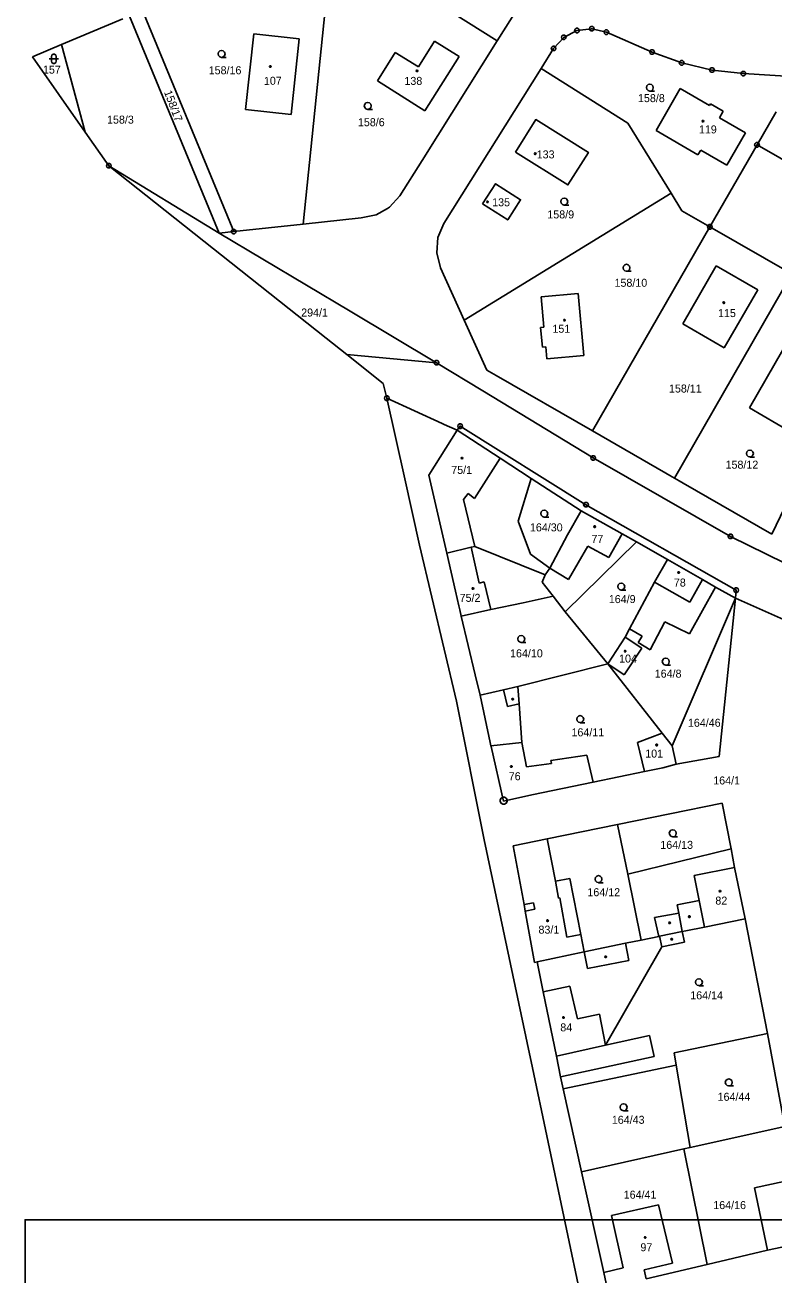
# Model space of a CAD drawing. Extents: x -779723 to -777378, y -1011169 to -1009297.
# Drawn here: x -779530.7 to -779371.6, y -1010279.6 to -1010014.1 of the extents above; entities that cross this region are included whole.
import ezdxf

# ---------------------------------------------------------------- set-up
doc = ezdxf.new("R2010")
doc.units = 0
for name, color, linetype in [('Default', 7, 'Continuous'), ('KN_HRANICE', 7, 'Continuous'), ('KN_KULTURY', 7, 'Continuous'), ('KN_PARCELY', 7, 'Continuous'), ('KN_SLUCKY', 7, 'Continuous'), ('LEGENDA', 7, 'Continuous')]:
    doc.layers.add(name, color=color, linetype=linetype)

# ---------------------------------------------------------------- blocks, each defined once
blk = doc.blocks.new('101')
at = {"layer": 'Default'}
blk.add_line((-0.05, 0), (0.05, 0), dxfattribs=at)
blk.add_lwpolyline([(0.19, 0.72), (0.53, 0.53), (0.72, 0.19), (0.72, -0.2), (0.53, -0.54), (0.19, -0.73), (-0.2, -0.73), (-0.54, -0.54), (-0.73, -0.2), (-0.73, 0.19), (-0.54, 0.53), (-0.2, 0.72), (0.19, 0.72)], dxfattribs=at)
blk = doc.blocks.new('304')
at = {"layer": 'Default'}
blk.add_lwpolyline([(0, 0), (-0.38, 0.1), (-0.65, 0.37), (-0.75, 0.74), (-0.65, 1.11), (-0.38, 1.38), (-0.01, 1.48), (0.36, 1.38), (0.63, 1.11), (0.73, 0.73), (0.63, 0.35), (0.36, 0.08), (-0.02, -0.02), (0.98, -0.02)], dxfattribs=at)
blk = doc.blocks.new('316')
at = {"layer": 'Default'}
for points in [[(-1, 1), (0.27, 1), (1, 1)], [(-0.5, 1.5), (-0.4, 1.79), (-0.15, 1.97), (0.16, 1.97), (0.41, 1.79), (0.51, 1.5), (0.51, 0.5), (0.41, 0.21), (0.16, 0.03), (-0.15, 0.03), (-0.4, 0.21), (-0.5, 0.5), (-0.5, 1.5)]]:
    blk.add_lwpolyline(points, dxfattribs=at)
blk = doc.blocks.new('402')
at = {"layer": 'Default'}
blk.add_lwpolyline([(0.09, 0.15), (0.18, 0), (0.09, -0.15), (-0.09, -0.15), (-0.18, 0), (-0.09, 0.15), (0.09, 0.15)], dxfattribs=at)
blk = doc.blocks.new('105')
at = {"layer": 'Default'}
blk.add_line((-0.12, 0), (0.12, 0), dxfattribs=at)
blk.add_lwpolyline([(0.15, 0.48), (0.4, 0.3), (0.5, 0.01), (0.4, -0.28), (0.15, -0.46), (-0.16, -0.46), (-0.41, -0.28), (-0.51, 0.01), (-0.41, 0.3), (-0.16, 0.48), (0.15, 0.48)], dxfattribs=at)

msp = doc.modelspace()

# ---------------------------------------------------------------- linework, layer by layer
at = {"layer": 'KN_HRANICE'}
for p, q in [((-779430.36, -1010017.45), (-779405.63, -1009978.11)), ((-779466.49, -1010007.04), (-779471.6, -1010056.37)), ((-779505.72, -1010011.01), (-779486.32, -1010057.97)), ((-779430.36, -1010017.45), (-779443.07, -1010009.46)), ((-779522.9, -1010018.23), (-779509.9, -1010012.78)), ((-779508.48, -1010012.18), (-779489.42, -1010058.31)), ((-779483.83, -1010032.01), (-779482.07, -1010015.94)), ((-779482.07, -1010015.94), (-779472.39, -1010016.99)), ((-779416.21, -1010016.69), (-779413.4, -1010015.24)), ((-779413.4, -1010015.24), (-779410.26, -1010014.85)), ((-779410.26, -1010014.85), (-779407.15, -1010015.59)), ((-779407.15, -1010015.59), (-779397.45, -1010019.81)), ((-779529.07, -1010020.81), (-779522.9, -1010018.23)), ((-779522.9, -1010018.23), (-779517.85, -1010036.84)), ((-779472.39, -1010016.99), (-779474.14, -1010033.11)), ((-779447.1, -1010022.98), (-779443.68, -1010017.51)), ((-779443.68, -1010017.51), (-779438.46, -1010020.79)), ((-779421.04, -1010023.31), (-779418.36, -1010019.05)), ((-779418.36, -1010019.05), (-779416.21, -1010016.69)), ((-779517.85, -1010036.84), (-779529.07, -1010020.81)), ((-779455.79, -1010025.95), (-779452.01, -1010019.89)), ((-779452.01, -1010019.89), (-779447.1, -1010022.98)), ((-779438.46, -1010020.79), (-779445.71, -1010032.28)), ((-779397.45, -1010019.81), (-779391.16, -1010022.12)), ((-779441.71, -1010056.21), (-779421.04, -1010023.31)), ((-779402.59, -1010034.91), (-779421.04, -1010023.31)), ((-779391.16, -1010022.12), (-779384.71, -1010023.64)), ((-779384.71, -1010023.64), (-779378.05, -1010024.4)), ((-779445.71, -1010032.28), (-779455.79, -1010025.95)), ((-779378.05, -1010024.4), (-779366.83, -1010025.07)), ((-779391.47, -1010027.58), (-779396.61, -1010036.51)), ((-779385.28, -1010031.16), (-779391.47, -1010027.58)), ((-779474.14, -1010033.11), (-779483.83, -1010032.01)), ((-779385.04, -1010030.79), (-779385.28, -1010031.16)), ((-779382.33, -1010032.39), (-779385.04, -1010030.79)), ((-779393.43, -1010049.78), (-779402.59, -1010034.91)), ((-779383.14, -1010033.8), (-779382.33, -1010032.39)), ((-779377.61, -1010036.95), (-779383.14, -1010033.8)), ((-779375.15, -1010039.53), (-779371.1, -1010032.49)), ((-779512.85, -1010043.97), (-779517.85, -1010036.84)), ((-779396.61, -1010036.51), (-779387.72, -1010041.66)), ((-779381.6, -1010043.83), (-779377.61, -1010036.95)), ((-779385.17, -1010056.96), (-779375.15, -1010039.53)), ((-779375.15, -1010039.53), (-779361.56, -1010047.34)), ((-779387.72, -1010041.66), (-779387.12, -1010040.63)), ((-779387.12, -1010040.63), (-779381.6, -1010043.83)), ((-779489.42, -1010058.31), (-779512.85, -1010043.97)), ((-779466.67, -1010080.62), (-779512.85, -1010043.97)), ((-779451.04, -1010050.34), (-779453.2, -1010052.79)), ((-779437.34, -1010076.8), (-779393.43, -1010049.78)), ((-779391.11, -1010053.54), (-779393.43, -1010049.78)), ((-779385.17, -1010056.96), (-779391.11, -1010053.54)), ((-779459.24, -1010055.03), (-779471.6, -1010056.37)), ((-779456.04, -1010054.41), (-779459.24, -1010055.03)), ((-779441.71, -1010056.21), (-779442.97, -1010059.22)), ((-779486.32, -1010057.97), (-779489.42, -1010058.31)), ((-779489.42, -1010058.31), (-779461.6, -1010074.87)), ((-779471.6, -1010056.37), (-779486.32, -1010057.97)), ((-779410.1, -1010100.31), (-779385.17, -1010056.96)), ((-779385.17, -1010056.96), (-779367.78, -1010066.96)), ((-779442.97, -1010059.22), (-779443.2, -1010062.48)), ((-779443.2, -1010062.48), (-779442.37, -1010065.63)), ((-779442.37, -1010065.63), (-779437.34, -1010076.8)), ((-779390.94, -1010077.53), (-779383.8, -1010065.23)), ((-779383.8, -1010065.23), (-779374.99, -1010070.35)), ((-779392.71, -1010110.31), (-779367.78, -1010066.96)), ((-779420.98, -1010071.8), (-779413.13, -1010071.11)), ((-779420.44, -1010078.28), (-779420.98, -1010071.8)), ((-779413.13, -1010071.11), (-779411.92, -1010084.25)), ((-779374.99, -1010070.35), (-779382.13, -1010082.68)), ((-779461.6, -1010074.87), (-779443.22, -1010085.81)), ((-779437.34, -1010076.8), (-779432.57, -1010087.39)), ((-779371.98, -1010122.22), (-779350.39, -1010076.96)), ((-779421.12, -1010078.36), (-779420.44, -1010078.28)), ((-779420.75, -1010082.53), (-779421.12, -1010078.36)), ((-779382.13, -1010082.68), (-779390.94, -1010077.53)), ((-779462.29, -1010084.1), (-779466.67, -1010080.62)), ((-779420.01, -1010082.47), (-779420.75, -1010082.53)), ((-779419.8, -1010084.97), (-779420.01, -1010082.47)), ((-779443.22, -1010085.81), (-779462.29, -1010084.1)), ((-779454.55, -1010090.24), (-779462.29, -1010084.1)), ((-779411.92, -1010084.25), (-779419.8, -1010084.97)), ((-779376.78, -1010095.43), (-779369.65, -1010083.1)), ((-779443.22, -1010085.81), (-779433.43, -1010091.77)), ((-779453.79, -1010093.36), (-779454.55, -1010090.24)), ((-779449.96, -1010110.52), (-779453.79, -1010093.36)), ((-779433.43, -1010091.77), (-779409.97, -1010106.05)), ((-779368.02, -1010100.51), (-779376.78, -1010095.43)), ((-779444.86, -1010109.68), (-779438.86, -1010100.16)), ((-779438.86, -1010100.16), (-779431.13, -1010105.19)), ((-779431.13, -1010105.19), (-779429.69, -1010106.11)), ((-779423.11, -1010110.38), (-779429.69, -1010106.11)), ((-779409.97, -1010106.05), (-779380.8, -1010122.72)), ((-779446.83, -1010124.56), (-779449.96, -1010110.52)), ((-779441.05, -1010126.3), (-779444.86, -1010109.68)), ((-779425.9, -1010119.46), (-779423.11, -1010110.38)), ((-779412.49, -1010117.26), (-779423.11, -1010110.38)), ((-779415.42, -1010122.39), (-779412.49, -1010117.26)), ((-779412.49, -1010117.26), (-779403.77, -1010122.18)), ((-779425.9, -1010119.46), (-779423.3, -1010126.5)), ((-779415.42, -1010122.39), (-779419.17, -1010129.45)), ((-779403.77, -1010122.18), (-779400.78, -1010123.88)), ((-779439.02, -1010157.72), (-779446.83, -1010124.56)), ((-779441.05, -1010126.3), (-779435.89, -1010125.03)), ((-779435.89, -1010125.03), (-779435.11, -1010124.84)), ((-779435.11, -1010124.84), (-779420.18, -1010130.88)), ((-779415.89, -1010138.74), (-779400.78, -1010123.88)), ((-779394.14, -1010127.63), (-779400.78, -1010123.88)), ((-779380.8, -1010122.72), (-779356.88, -1010134.5)), ((-779439.21, -1010134.38), (-779441.05, -1010126.3)), ((-779419.17, -1010129.45), (-779423.3, -1010126.5)), ((-779396.93, -1010132.43), (-779394.14, -1010127.63)), ((-779386.76, -1010131.89), (-779394.14, -1010127.63)), ((-779419.17, -1010129.45), (-779420.18, -1010130.88)), ((-779420.18, -1010130.88), (-779420.81, -1010132.43)), ((-779420.81, -1010132.43), (-779418.47, -1010135.43)), ((-779396.93, -1010132.43), (-779402.22, -1010142.37)), ((-779386.76, -1010131.89), (-779384.01, -1010133.48)), ((-779438.5, -1010137.45), (-779439.21, -1010134.38)), ((-779424.85, -1010136.8), (-779418.47, -1010135.43)), ((-779415.89, -1010138.74), (-779418.47, -1010135.43)), ((-779393.19, -1010167.19), (-779379.75, -1010135.84)), ((-779384.01, -1010133.48), (-779389.49, -1010143.43)), ((-779384.01, -1010133.48), (-779379.75, -1010135.84)), ((-779379.75, -1010135.84), (-779383.22, -1010169.47)), ((-779379.75, -1010135.84), (-779368.25, -1010140.93)), ((-779438.29, -1010138.35), (-779438.5, -1010137.45)), ((-779438.03, -1010139.63), (-779438.29, -1010138.35)), ((-779431.67, -1010138.26), (-779438.03, -1010139.63)), ((-779424.85, -1010136.8), (-779431.67, -1010138.26)), ((-779438.03, -1010139.63), (-779435, -1010152.13)), ((-779415.89, -1010138.74), (-779406.87, -1010149.81)), ((-779394.77, -1010140.85), (-779397.87, -1010146.79)), ((-779389.49, -1010143.43), (-779394.77, -1010140.85)), ((-779402.22, -1010142.37), (-779403.16, -1010144.15)), ((-779399.58, -1010143.89), (-779402.22, -1010142.37)), ((-779406.87, -1010149.81), (-779403.16, -1010144.15)), ((-779399.6, -1010146.43), (-779403.35, -1010152.12)), ((-779403.16, -1010144.15), (-779399.6, -1010146.43)), ((-779400.38, -1010145.27), (-779399.58, -1010143.89)), ((-779397.87, -1010146.79), (-779400.38, -1010145.27)), ((-779425.97, -1010154.58), (-779406.87, -1010149.81)), ((-779403.35, -1010152.12), (-779406.87, -1010149.81)), ((-779406.87, -1010149.81), (-779395.28, -1010164.54)), ((-779435, -1010152.13), (-779433.96, -1010156.43)), ((-779433.96, -1010156.43), (-779428.99, -1010155.28)), ((-779433.96, -1010156.43), (-779431.85, -1010166.47)), ((-779428.99, -1010155.28), (-779425.97, -1010154.58)), ((-779425.7, -1010158.32), (-779425.97, -1010154.58)), ((-779433.12, -1010187.16), (-779439.02, -1010157.72)), ((-779425.12, -1010166.48), (-779425.7, -1010158.32)), ((-779400.55, -1010166.52), (-779395.28, -1010164.54)), ((-779395.28, -1010164.54), (-779393.19, -1010167.19)), ((-779431.85, -1010166.47), (-779431.68, -1010167.23)), ((-779431.68, -1010167.23), (-779431.65, -1010167.35)), ((-779431.65, -1010167.35), (-779429.01, -1010178.94)), ((-779425.12, -1010166.48), (-779424.13, -1010171.7)), ((-779399.03, -1010172.67), (-779400.55, -1010166.52)), ((-779393.19, -1010167.19), (-779392.31, -1010171.12)), ((-779418.94, -1010170.34), (-779411.28, -1010169.22)), ((-779418.85, -1010170.93), (-779418.94, -1010170.34)), ((-779411.28, -1010169.22), (-779409.96, -1010174.94)), ((-779392.31, -1010171.12), (-779383.22, -1010169.47)), ((-779424.13, -1010171.7), (-779418.85, -1010170.93)), ((-779399.03, -1010172.67), (-779409.96, -1010174.94)), ((-779395.19, -1010171.87), (-779399.03, -1010172.67)), ((-779395.19, -1010171.87), (-779392.31, -1010171.12)), ((-779409.96, -1010174.94), (-779423, -1010177.65)), ((-779429.01, -1010178.94), (-779423, -1010177.65)), ((-779404.79, -1010183.9), (-779382.53, -1010179.37)), ((-779382.53, -1010179.37), (-779380.62, -1010189.12)), ((-779419.77, -1010186.97), (-779404.79, -1010183.9)), ((-779404.79, -1010183.9), (-779402.63, -1010194.49)), ((-779423.51, -1010232.67), (-779433.12, -1010187.16)), ((-779426.94, -1010188.44), (-779419.77, -1010186.97)), ((-779426.94, -1010188.44), (-779424.65, -1010200.94)), ((-779418, -1010195.98), (-779419.77, -1010186.97)), ((-779380.62, -1010189.12), (-779402.63, -1010194.49)), ((-779380.62, -1010189.12), (-779379.91, -1010193.08)), ((-779379.91, -1010193.08), (-779377.71, -1010203.99)), ((-779418, -1010195.98), (-779414.94, -1010195.39)), ((-779414.94, -1010195.39), (-779412.61, -1010207.26)), ((-779402.63, -1010194.49), (-779399.78, -1010208.48)), ((-779424.65, -1010200.94), (-779424.4, -1010202.32)), ((-779424.4, -1010202.32), (-779422.41, -1010213.23)), ((-779377.71, -1010203.99), (-779386.3, -1010205.71)), ((-779377.71, -1010203.99), (-779372.96, -1010228.31)), ((-779412.61, -1010207.26), (-779411.88, -1010211.01)), ((-779391.03, -1010206.67), (-779395.84, -1010207.67)), ((-779390.31, -1010206.52), (-779391.03, -1010206.67)), ((-779390.58, -1010208.93), (-779391.03, -1010206.67)), ((-779386.3, -1010205.71), (-779390.31, -1010206.52)), ((-779411.88, -1010211.01), (-779403.09, -1010209.16)), ((-779407.33, -1010230.83), (-779395.35, -1010209.92)), ((-779403.09, -1010209.16), (-779399.78, -1010208.48)), ((-779399.78, -1010208.48), (-779396.04, -1010207.71)), ((-779395.84, -1010207.67), (-779396.04, -1010207.71)), ((-779395.35, -1010209.92), (-779390.58, -1010208.93)), ((-779421.87, -1010213.12), (-779411.88, -1010211.01)), ((-779422.41, -1010213.23), (-779421.87, -1010213.12)), ((-779421.87, -1010213.12), (-779420.58, -1010219.44)), ((-779420.58, -1010219.44), (-779417.77, -1010233.17)), ((-779407.33, -1010230.83), (-779397.99, -1010228.74)), ((-779396.99, -1010233.24), (-779397.99, -1010228.74)), ((-779372.96, -1010228.31), (-779392.78, -1010232.41)), ((-779369.26, -1010248.05), (-779372.96, -1010228.31)), ((-779423.17, -1010234.28), (-779423.51, -1010232.67)), ((-779417.77, -1010233.17), (-779416.88, -1010237.53)), ((-779416.88, -1010237.53), (-779396.99, -1010233.24)), ((-779392.32, -1010235.07), (-779392.78, -1010232.41)), ((-779411.57, -1010289.24), (-779423.17, -1010234.28)), ((-779416.36, -1010240.08), (-779392.32, -1010235.07)), ((-779389.34, -1010252.55), (-779392.32, -1010235.07)), ((-779416.88, -1010237.53), (-779416.36, -1010240.08)), ((-779416.36, -1010240.08), (-779412.45, -1010257.73)), ((-779369.26, -1010248.05), (-779389.34, -1010252.55)), ((-779389.34, -1010252.55), (-779390.67, -1010252.85)), ((-779390.67, -1010252.85), (-779412.45, -1010257.73)), ((-779385.75, -1010277.38), (-779390.67, -1010252.85)), ((-779412.45, -1010257.73), (-779407.72, -1010279.08)), ((-779375.67, -1010261.12), (-779366.85, -1010259.23)), ((-779372.96, -1010274.36), (-779375.67, -1010261.12)), ((-779406.08, -1010266.98), (-779396.07, -1010264.73)), ((-779396.07, -1010264.73), (-779393.09, -1010277.12)), ((-779406.08, -1010266.98), (-779403.57, -1010278.12)), ((-779363.99, -1010272.5), (-779372.96, -1010274.36)), ((-779372.96, -1010274.36), (-779385.75, -1010277.38)), ((-779407.72, -1010279.08), (-779403.57, -1010278.12)), ((-779407.72, -1010279.08), (-779406.99, -1010282.4)), ((-779399.16, -1010278.51), (-779393.09, -1010277.12)), ((-779399.16, -1010278.51), (-779398.69, -1010280.44)), ((-779385.75, -1010277.38), (-779398.69, -1010280.44))]:
    msp.add_line(p, q, dxfattribs=at)
for points in [[(-779430.36, -1010017.45), (-779446.32, -1010042.84), (-779451.04, -1010050.34)], [(-779453.2, -1010052.79), (-779453.68, -1010053.07), (-779456.04, -1010054.41)], [(-779432.57, -1010087.39), (-779430.6, -1010088.52), (-779410.1, -1010100.31)], [(-779453.79, -1010093.36), (-779442.04, -1010098.71), (-779441.59, -1010098.92), (-779438.86, -1010100.16)], [(-779410.1, -1010100.31), (-779394.52, -1010109.27), (-779393.65, -1010109.77), (-779392.71, -1010110.31)], [(-779392.71, -1010110.31), (-779391.69, -1010110.89), (-779390.82, -1010111.39), (-779371.98, -1010122.22)]]:
    msp.add_lwpolyline(points, dxfattribs=at)
for points in [[(-779426.49, -1010041.07), (-779422.15, -1010034.15), (-779410.97, -1010041.14), (-779415.34, -1010048.05)], [(-779433.48, -1010052.09), (-779430.71, -1010047.79), (-779425.37, -1010051.19), (-779428.1, -1010055.49)]]:
    msp.add_lwpolyline(points, close=True, dxfattribs=at)
at = {"layer": 'KN_SLUCKY'}
for p, q in [((-779438.22, -1010099.31), (-779438.86, -1010100.16)), ((-779411.49, -1010115.98), (-779438.22, -1010099.31)), ((-779429.69, -1010106.11), (-779435.16, -1010114.65)), ((-779436.55, -1010113.62), (-779437.52, -1010114.87)), ((-779435.16, -1010114.65), (-779436.55, -1010113.62)), ((-779437.52, -1010114.87), (-779435.11, -1010124.84)), ((-779379.59, -1010134.15), (-779411.49, -1010115.98)), ((-779403.77, -1010122.18), (-779406.62, -1010127.23)), ((-779434.17, -1010132.62), (-779435.89, -1010125.03)), ((-779415.18, -1010131.88), (-779411.09, -1010124.77)), ((-779411.09, -1010124.77), (-779406.62, -1010127.23)), ((-779419.17, -1010129.45), (-779415.18, -1010131.88)), ((-779433.09, -1010132.38), (-779434.17, -1010132.62)), ((-779431.67, -1010138.26), (-779433.09, -1010132.38)), ((-779396.93, -1010132.43), (-779389.44, -1010136.7)), ((-779389.44, -1010136.7), (-779386.76, -1010131.89)), ((-779379.75, -1010135.84), (-779379.59, -1010134.15)), ((-779428.99, -1010155.28), (-779428.14, -1010158.86)), ((-779428.14, -1010158.86), (-779425.7, -1010158.32)), ((-779431.68, -1010167.23), (-779425.12, -1010166.48)), ((-779379.91, -1010193.08), (-779388.53, -1010194.78)), ((-779417.3, -1010199.54), (-779418, -1010195.98)), ((-779388.53, -1010194.78), (-779387.44, -1010200.1)), ((-779417.3, -1010199.54), (-779417.02, -1010199.49)), ((-779417.02, -1010199.49), (-779415.55, -1010207.86)), ((-779424.65, -1010200.94), (-779422.61, -1010200.55)), ((-779424.4, -1010202.32), (-779422.35, -1010201.94)), ((-779422.35, -1010201.94), (-779422.61, -1010200.55)), ((-779392.14, -1010201.01), (-779387.44, -1010200.1)), ((-779391.8, -1010202.74), (-779392.14, -1010201.01)), ((-779387.44, -1010200.1), (-779386.3, -1010205.71)), ((-779396.93, -1010203.68), (-779391.8, -1010202.74)), ((-779396.93, -1010203.68), (-779396.04, -1010207.71)), ((-779391.03, -1010206.67), (-779391.8, -1010202.74)), ((-779415.55, -1010207.86), (-779412.61, -1010207.26)), ((-779403.09, -1010209.16), (-779402.38, -1010212.79)), ((-779395.84, -1010207.67), (-779395.35, -1010209.92)), ((-779411.88, -1010211.01), (-779411.2, -1010214.51)), ((-779411.2, -1010214.51), (-779402.38, -1010212.79)), ((-779420.58, -1010219.44), (-779414.92, -1010218.29)), ((-779413.31, -1010225.22), (-779414.92, -1010218.29)), ((-779413.31, -1010225.22), (-779408.6, -1010224.25)), ((-779407.33, -1010230.83), (-779408.6, -1010224.25)), ((-779417.77, -1010233.17), (-779407.33, -1010230.83))]:
    msp.add_line(p, q, dxfattribs=at)
at = {"layer": 'LEGENDA'}
msp.add_lwpolyline([(-779530.66, -1010687.91), (-778936.66, -1010687.91), (-778936.66, -1010267.91), (-779530.66, -1010267.91)], close=True, dxfattribs=at)

# ---------------------------------------------------------------- block references
at = {"layer": 'KN_KULTURY'}
for name, p in [('316', (-779524.53, -1010022.26)), ('304', (-779488.9, -1010020.94)), ('402', (-779478.55, -1010022.91)), ('402', (-779447.37, -1010023.8)), ('304', (-779397.92, -1010028.1)), ('304', (-779457.85, -1010031.99)), ('402', (-779386.65, -1010034.5)), ('402', (-779422.27, -1010041.41)), ('304', (-779416.09, -1010052.31)), ('402', (-779432.4, -1010051.64)), ('304', (-779402.87, -1010066.38)), ('402', (-779382.22, -1010073.06)), ('402', (-779416.04, -1010076.77)), ('402', (-779437.84, -1010106.08)), ('304', (-779376.66, -1010105.84)), ('304', (-779420.36, -1010118.61)), ('402', (-779409.66, -1010120.65)), ('402', (-779391.79, -1010130.39)), ('304', (-779404, -1010134.11)), ('402', (-779435.51, -1010133.78)), ('304', (-779425.24, -1010145.25)), ('402', (-779403.16, -1010147.09)), ('304', (-779394.55, -1010150.05)), ('402', (-779427.06, -1010157.27)), ('304', (-779412.71, -1010162.28)), ('402', (-779396.49, -1010167.04)), ('402', (-779427.35, -1010171.61)), ('304', (-779393.06, -1010186.52)), ('304', (-779408.82, -1010196.27)), ('402', (-779383.02, -1010198.11)), ('402', (-779419.66, -1010204.35)), ('402', (-779393.73, -1010204.81)), ('402', (-779389.53, -1010203.5)), ('402', (-779393.27, -1010208.3)), ('402', (-779407.31, -1010212.04)), ('304', (-779387.49, -1010218.16)), ('402', (-779416.27, -1010224.92)), ('304', (-779381.14, -1010239.45)), ('304', (-779403.48, -1010244.74)), ('402', (-779398.92, -1010271.64))]:
    msp.add_blockref(name, p, dxfattribs=at)
at = {"layer": 'KN_PARCELY'}
for name, p in [('105', (-779416.21, -1010016.69)), ('105', (-779413.4, -1010015.24)), ('105', (-779410.26, -1010014.85)), ('105', (-779407.15, -1010015.59)), ('105', (-779418.36, -1010019.05)), ('105', (-779397.45, -1010019.81)), ('105', (-779391.16, -1010022.12)), ('105', (-779384.71, -1010023.64)), ('105', (-779378.05, -1010024.4)), ('105', (-779375.15, -1010039.53)), ('105', (-779512.85, -1010043.97)), ('105', (-779486.32, -1010057.97)), ('105', (-779385.17, -1010056.96)), ('105', (-779443.22, -1010085.81)), ('105', (-779453.79, -1010093.36)), ('105', (-779438.22, -1010099.31)), ('105', (-779409.97, -1010106.05)), ('105', (-779411.49, -1010115.98)), ('105', (-779380.8, -1010122.72)), ('105', (-779379.59, -1010134.15)), ('101', (-779428.97, -1010178.86))]:
    msp.add_blockref(name, p, dxfattribs=at)

# ---------------------------------------------------------------- texts
for s, p in [('157', (-779526.85, -1010024.4)), ('158/16', (-779491.64, -1010024.54)), ('138', (-779450.06, -1010026.79)), ('158/8', (-779400.44, -1010030.45)), ('158/3', (-779513.23, -1010035.02)), ('158/6', (-779459.94, -1010035.57)), ('119', (-779387.5, -1010037.1)), ('133', (-779421.96, -1010042.41)), ('135', (-779431.42, -1010052.58)), ('158/9', (-779419.7, -1010055.16)), ('158/10', (-779405.43, -1010069.68)), ('294/1', (-779471.99, -1010076)), ('115', (-779383.44, -1010076.12)), ('151', (-779418.62, -1010079.45)), ('158/11', (-779393.86, -1010092.15)), ('158/12', (-779381.84, -1010108.33)), ('75/1', (-779440.11, -1010109.44)), ('164/30', (-779423.4, -1010121.65)), ('77', (-779410.33, -1010124.09)), ('78', (-779392.82, -1010133.37)), ('75/2', (-779438.33, -1010136.62)), ('164/9', (-779406.64, -1010136.88)), ('164/10', (-779427.62, -1010148.41)), ('104', (-779404.46, -1010149.52)), ('164/8', (-779396.89, -1010152.72)), ('164/46', (-779389.84, -1010163.16)), ('164/11', (-779414.57, -1010165.19)), ('101', (-779398.91, -1010169.71)), ('76', (-779427.9, -1010174.52)), ('164/1', (-779384.46, -1010175.42)), ('164/13', (-779395.7, -1010189.1)), ('164/12', (-779411.19, -1010199.16)), ('82', (-779384.01, -1010200.94)), ('83/1', (-779421.58, -1010207.11)), ('164/14', (-779389.34, -1010221.07)), ('84', (-779416.95, -1010227.88)), ('164/44', (-779383.53, -1010242.62)), ('164/43', (-779406, -1010247.51)), ('164/41', (-779403.48, -1010263.42)), ('164/16', (-779384.45, -1010265.63)), ('97', (-779399.93, -1010274.59))]:
    msp.add_text(s, height=1.7, dxfattribs=at).set_placement(p)
for s, rotation, p in [('107', 0.802, (-779479.9, -1010026.79)), ('158/17', 290.661, (-779501.16, -1010028.3))]:
    msp.add_text(s, height=1.7, rotation=rotation, dxfattribs=at).set_placement(p)

doc.saveas('drawing.dxf')
